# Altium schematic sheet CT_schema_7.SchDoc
size 277 x 170 mm
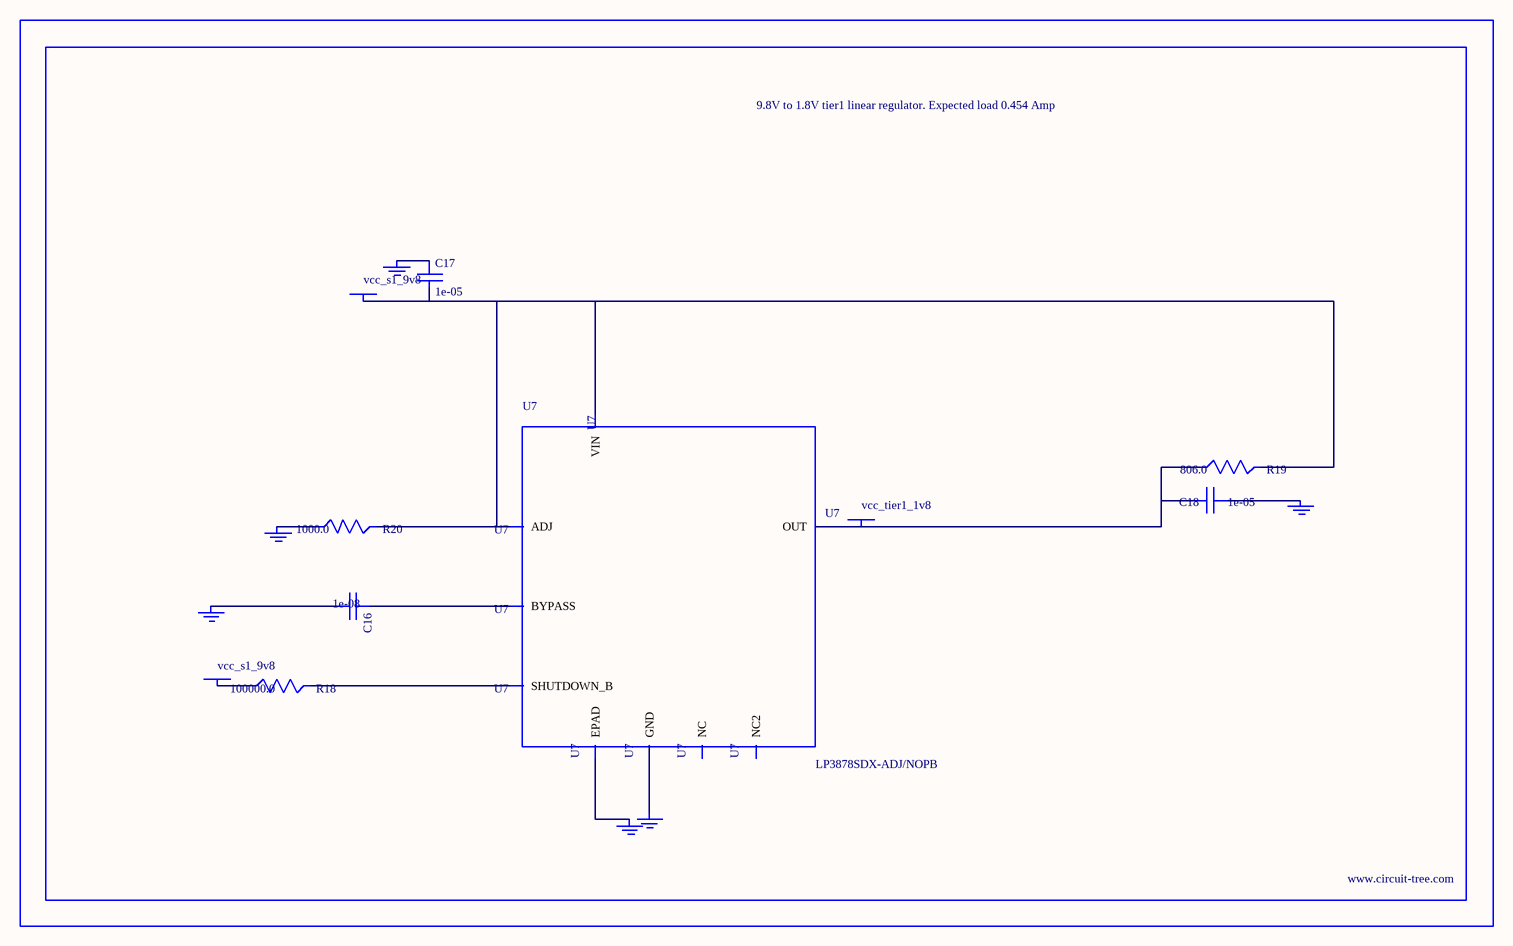
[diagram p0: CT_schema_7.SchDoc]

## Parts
BORDER6  (no value)
C16  1e-08  [C0402]
C17  1e-05  [C1206]
C18  1e-05  [C0805]
GND_INSTANCE_6_0  (no value)
GND_INSTANCE_6_1  (no value)
GND_INSTANCE_6_2  (no value)
GND_INSTANCE_6_3  (no value)
GND_INSTANCE_6_4  (no value)
GND_INSTANCE_6_5  (no value)
POWER_INSTANCE_6_0  vcc_s1_9v8
POWER_INSTANCE_6_1  vcc_s1_9v8
POWER_INSTANCE_6_2  vcc_tier1_1v8
R18  100000.0  [R0603]
R19  806.0  [R0603]
R20  1000.0  [R0603]
U7  LP3878SDX-ADJ/NOPB  [WSON-8]

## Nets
NetC16_1: C16.1 U7.1(BYPASS)
NetC16_2: C16.2 GND_INSTANCE_6_0.0(GND)
NetC17_1: C17.1 GND_INSTANCE_6_1.0(GND)
NetC17_2: C17.2 POWER_INSTANCE_6_0.0(PWR) R19.2 R20.2 U7.4(VIN) U7.6(ADJ)
NetC18_1: C18.1 GND_INSTANCE_6_2.0(GND)
NetC18_2: C18.2 POWER_INSTANCE_6_2.0(PWR) R19.1 U7.5(OUT)
NetGND_INSTANCE_6_3_0: GND_INSTANCE_6_3.0(GND) R20.1
NetGND_INSTANCE_6_4_0: GND_INSTANCE_6_4.0(GND) U7.PAD(EPAD)
NetGND_INSTANCE_6_5_0: GND_INSTANCE_6_5.0(GND) U7.3(GND)
NetPOWER_INSTANCE_6_1_0: POWER_INSTANCE_6_1.0(PWR) R18.1
NetR18_2: R18.2 U7.8(SHUTDOWN_B)

Not connected (* = marked no-connect by the designer): U7 2(NC) 7(NC2)

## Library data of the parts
BORDER6 = BORDER_PAGE6
C16 = C0402C103K3RAC
C17 = C1206C106K3RACTU
C18 = GRM219R60J106ME19D
GND_INSTANCE_6_0-GND_INSTANCE_6_5 = GND
POWER_INSTANCE_6_0-POWER_INSTANCE_6_2 = PWR
R18 = RC0603JR-07100KL
R19 = ERJ-3EKF8060V
R20 = RC0603JR-071KL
